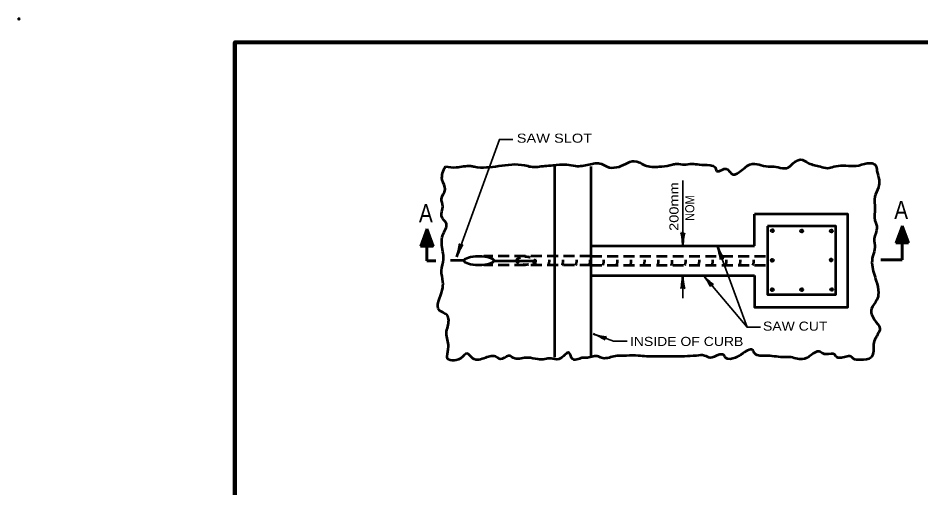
# Model space of a CAD drawing. Extents: x -90 to 623, y -379 to 75.
# Drawn here: x -90.3 to 108.4, y -28.7 to 74.7 of the extents above; entities that cross this region are included whole.
import ezdxf

# ---------------------------------------------------------------- set-up
doc = ezdxf.new("R2010")
doc.units = 0
doc.header["$LTSCALE"] = 0.8
doc.header["$PDMODE"] = 32
doc.header["$PDSIZE"] = 0.4
doc.linetypes.add('MEDIUM_DASHED', pattern=[4.5, 3, -1.5])
doc.linetypes.add('SHORT_DASHED', pattern=[2.7, 1.5, -1.2])
doc.layers.add('1', color=7, linetype='Continuous', lineweight=35)

msp = doc.modelspace()

# ---------------------------------------------------------------- linework, layer by layer
at = {"layer": '1', "lineweight": 53}
for p, q in [((27.7826, 42.0557), (27.7826, 0.0557)), ((35.7826, 42.0557), (35.7826, 0.0557)), ((71.7826, 24.5557), (71.7826, 31.5557)), ((-0.3066, 28.2745), (-1.6747, 24.5158)), ((-0.3066, 28.2745), (1.0615, 24.5158)), ((104.2712, 28.9673), (102.9032, 25.2086)), ((104.2712, 28.9673), (105.6393, 25.2086)), ((35.7826, 24.5557), (71.7826, 24.5557)), ((102.9032, 25.2086), (105.6393, 25.2086)), ((7.8699, 21.3127), (4.8699, 21.3127)), ((14.3764, 21.2934), (23.4164, 21.2934)), ((35.7826, 18.0557), (71.7826, 18.0557))]:
    msp.add_line(p, q, dxfattribs=at)
at = {"layer": '1'}
for p, q in [((56.0009, 24.5898), (56.0009, 38.9634)), ((63.6731, 24.3975), (70.135, 6.6434)), ((56.0009, 13.0557), (56.0009, 18.039))]:
    msp.add_line(p, q, dxfattribs=at)
at = {"layer": '1', "lineweight": 60}
for p, q in [((-0.3066, 21.2745), (-0.3066, 28.2745)), ((104.2712, 21.4673), (104.2712, 28.9673)), ((-1.6747, 24.5158), (1.0615, 24.5158)), ((-0.3066, 21.2745), (1.6934, 21.2745)), ((99.5571, 21.4673), (104.2712, 21.4673))]:
    msp.add_line(p, q, dxfattribs=at)
at = {"layer": '1', "linetype": 'MEDIUM_DASHED', "lineweight": 53}
for p, q in [((35.7826, 22.3057), (12.2447, 22.3057)), ((35.7826, 22.3057), (74.6402, 22.3057)), ((35.7826, 20.3057), (12.2447, 20.3057)), ((35.7826, 20.3057), (74.6402, 20.3057))]:
    msp.add_line(p, q, dxfattribs=at)
at = {"layer": '1', "lineweight": 158}
msp.add_lwpolyline([(617.1938, 69.4188), (-42.5562, 69.3355), (-42.4728, -368.9978)], dxfattribs=at)
at = {"layer": '1'}
for points in [[(6.2503, 22.1841), (15.6422, 47.9881), (18.6423, 47.9881)], [(60.5589, 18.0557), (70.135, 6.6434), (73.135, 6.6434)], [(36.3312, 5.1835), (40.7482, 3.5757), (43.7482, 3.5757)]]:
    msp.add_lwpolyline(points, dxfattribs=at)
at = {"layer": '1', "lineweight": 53}
for points in [[(71.7826, 18.0557), (71.7826, 11.0557), (92.2826, 11.0557), (92.2826, 31.5557), (71.7826, 31.5557)], [(104.893, 26.9856), (103.703, 27.0432), (104.8162, 27.1007), (103.703, 27.1583), (104.7394, 27.1775), (103.7606, 27.2351), (104.7011, 27.2542), (103.8566, 27.3311), (104.7011, 27.3694), (103.7797, 27.427), (104.6435, 27.4846), (103.8757, 27.523), (104.6627, 27.5422), (103.8566, 27.6382), (104.5475, 27.6382), (103.9333, 27.7342), (104.5859, 27.7342), (103.9909, 27.8109), (104.4899, 27.8877), (104.0101, 27.8877), (104.4707, 27.9644), (104.0868, 28.0412), (104.4707, 28.0988), (104.0101, 27.9644), (104.394, 28.1947), (104.0485, 28.1372), (104.4132, 28.3099), (104.0868, 28.2907), (104.3556, 28.3867), (104.202, 28.4443), (104.3364, 28.5211), (104.1828, 28.6363), (103.012, 25.3157), (104.2404, 28.5787), (103.0696, 25.3541), (104.2596, 28.4443), (103.2232, 25.4117), (103.9909, 27.7149), (103.0888, 25.4117), (104.3364, 28.617)], [(104.3364, 28.617), (105.5264, 25.2773), (104.3364, 28.4251), (105.4112, 25.4692), (104.4323, 27.9261), (105.2193, 25.738), (104.3172, 28.0412), (105.0657, 25.9108), (104.7011, 25.8532), (105.1809, 25.6612), (103.2807, 25.6037), (103.2999, 25.7188), (103.607, 25.738), (103.7414, 26.0067), (103.4727, 26.0451), (105.488, 25.3733), (105.0466, 25.9683), (103.7414, 26.0067), (103.5878, 26.1987), (103.0504, 25.3925), (103.8757, 27.2735)], [(102.9928, 25.2773), (105.488, 25.2773), (105.4688, 25.3733), (103.0504, 25.3541), (105.392, 25.4309), (103.0504, 25.4501), (105.3537, 25.5077), (103.1272, 25.5652), (105.3152, 25.6228), (103.2232, 25.5268), (105.4112, 25.5268), (105.2768, 25.738), (103.1656, 25.6804), (105.2577, 25.8148), (103.2615, 25.8148), (105.1425, 25.9491), (103.2999, 25.9299), (105.2193, 26.0259), (103.3767, 26.0642), (105.1617, 26.1411), (103.3767, 26.1794), (105.1425, 26.2178), (103.3959, 26.2754), (105.0657, 26.3138), (103.3959, 26.3522), (105.0466, 26.3714), (103.5302, 26.4097), (105.0273, 26.4673), (103.4727, 26.4673), (104.9506, 26.5825), (103.4918, 26.5442), (104.9314, 26.6593), (103.4918, 26.6209), (104.9506, 26.7361), (103.5302, 26.7168), (104.9506, 26.832), (103.5687, 26.8128), (104.893, 26.9088), (103.607, 26.928), (104.893, 26.9856)]]:
    msp.add_lwpolyline(points, dxfattribs=at)
msp.add_lwpolyline([(74.6402, 28.8667), (74.6402, 13.8667), (89.6402, 13.8667), (89.6402, 28.8667)], close=True, dxfattribs=at)
at = {"layer": '1', "lineweight": 60}
msp.add_lwpolyline([(-1.4583, 24.7103), (0.7682, 24.7487), (0.6914, 24.9406), (-1.3815, 24.9022), (0.5762, 25.1709), (-1.3047, 25.1326), (0.5379, 25.3629), (-1.1895, 25.3629), (0.4995, 25.5932), (-1.1127, 25.6316), (0.4227, 25.8235), (-1.036, 25.8619), (0.154, 26.0538), (-1.0744, 26.1306), (0.3076, 26.0922), (-0.8441, 26.3609), (0.1924, 26.3993), (-0.7672, 26.5528), (-0.0763, 26.5528), (-0.6905, 26.7064), (-0.0379, 26.8216), (-0.6138, 26.8983), (-0.0763, 26.8983), (-0.4986, 26.9752), (-0.4218, 27.5509), (-1.4967, 24.5952), (-0.4218, 27.6661), (-0.0379, 27.0135), (0.9217, 24.6719), (0.2692, 25.67), (0.9985, 24.5567), (0.9217, 24.6335), (0.7682, 24.8254), (-0.0763, 26.7832), (-0.3067, 27.7045), (-0.1147, 27.2438), (-0.2298, 26.2842)], dxfattribs=at)
at = {"layer": '1', "lineweight": 53}
for centre in [(75.7151, 27.8881), (82.1636, 27.8497), (88.6889, 27.8497), (75.6767, 21.4012), (88.6505, 21.4395), (75.6767, 14.9142), (82.1636, 14.9142), (88.7657, 14.9526)]:
    msp.add_circle(centre, 0.25, dxfattribs=at)
at = {"layer": '1', "linetype": 'SHORT_DASHED', "lineweight": 53}
for centre in [(21.4742, 21.2253), (24.4874, 21.2445), (27.5005, 21.2061), (30.5138, 21.2445), (33.4694, 21.2253), (36.4826, 21.2445), (39.4766, 21.2445), (42.4898, 21.2061), (45.4645, 21.2254), (48.5161, 21.2061), (51.5293, 21.187), (54.5041, 21.2254), (57.4981, 21.2445), (60.4729, 21.2254), (63.4669, 21.2062), (66.5185, 21.2062), (69.4743, 21.2254)]:
    msp.add_arc(centre, 2.1707, 334.94384, 29.7373, dxfattribs=at)
at = {"layer": '1', "lineweight": 40}
for centre, major_axis, ratio, start_param, end_param in [((55.7246, 25.681), (0.1562, -1.7857), 0.122415, 0.89635335, 3.14159265), ((56.2125, 25.7103), (0.1757, 1.7565), 0.07063, 6.28230741, 8.55970261), ((6.3639, 23.304), (-0.464, -1.7314), 0.122415, 0.89635335, 3.14159265), ((6.8324, 23.1646), (0.7658, 1.5904), 0.07063, 6.28230741, 8.55970261), ((63.8575, 23.2722), (-0.4357, 1.7106), 0.07063, 3.14071475, 5.41810995), ((64.3059, 23.4666), (-0.7575, 1.6246), 0.122415, 0.89635335, 3.14159265), ((55.7893, 16.9185), (-0.1757, -1.7565), 0.07063, 6.28230741, 8.55970261), ((56.2772, 16.9478), (-0.1562, 1.7857), 0.122415, 0.89635335, 3.14159265), ((61.1171, 17.0613), (0.9945, -1.4584), 0.07063, 6.28230741, 8.55970261), ((61.1171, 17.0613), (0.9945, -1.4584), 0.07063, 6.28230741, 8.55970261), ((61.472, 17.3974), (-1.2674, 1.2675), 0.122415, 0.89635335, 3.14159265), ((61.472, 17.3974), (-1.2674, 1.2675), 0.122415, 0.89635335, 3.14159265), ((37.3118, 4.6014), (1.5904, -0.7658), 0.07063, 6.28230741, 8.55970261), ((37.4511, 5.0699), (-1.7314, 0.464), 0.122415, 0.89635335, 3.14159265)]:
    msp.add_ellipse(centre, major_axis=major_axis, ratio=ratio, start_param=start_param, end_param=end_param, dxfattribs=at)
at = {"layer": '1', "lineweight": 53}
msp.add_ellipse((11.1456, 21.3057), major_axis=(-3.25, 0), ratio=0.300371, dxfattribs=at)
at = {"layer": '1', "linetype": 'SHORT_DASHED', "lineweight": 53}
msp.add_ellipse((21.4166, 21.3057), major_axis=(-2, 0), ratio=0.452986, dxfattribs=at)
at = {"layer": '1', "lineweight": 53}
for points in [[(97.6571, 42.7712), (98.4248, 42.3105), (98.7319, 41.0822), (99.1925, 39.086), (99.039, 37.397), (98.2712, 35.4008), (98.2712, 32.7906), (98.2712, 30.1802), (98.7319, 28.4912), (98.1177, 26.188), (98.2712, 24.1918), (97.8106, 22.3492), (97.6571, 20.3532), (98.5783, 16.8216), (99.039, 14.2112), (98.7319, 12.6757), (97.5035, 10.6797), (98.1177, 8.3764), (99.3461, 6.3803), (98.1177, 3.6164), (97.8106, 0.699), (97.5035, 0.0848), (95.0468, -0.5293), (93.5113, -0.2223), (93.2042, 0.0848), (90.9009, -0.0687), (89.6726, 0.2384), (89.519, 0.5455), (87.5229, 0.699), (86.9087, 0.8526), (85.9874, 1.3133), (84.2983, 0.5455), (82.3023, -0.3758), (79.3848, 0.0848), (78.0029, 0.0848), (74.3178, 0.3919), (72.9358, 0.3919), (71.861, 0.8526), (71.4003, 1.6203), (68.9436, 0.699), (68.4829, 0.3919), (67.5617, -0.0687), (65.412, -0.0687), (64.9513, 0.5455), (63.8765, 0.5455), (62.0339, -0.0687), (60.8055, 0.3919), (58.9629, 0.3919), (56.3527, 0.2384), (54.6636, 0.2384), (51.5927, 0.2384), (49.5965, 0.2384), (48.0611, 0.2384), (46.2185, 0.3919), (43.6082, 0.3919), (40.8443, 0.2384), (38.0804, -0.0687), (37.4663, 0.2384), (35.0095, -0.0687), (34.0882, -0.0687), (33.0133, -0.3758), (31.785, -0.3758), (31.0173, 1.0061), (28.714, -0.3758), (27.025, -0.2223), (25.6431, -0.3758), (24.1076, -0.3758), (21.9579, -0.0687), (20.4224, -0.2223), (19.0405, -0.2223), (17.6586, 0.3919), (15.816, -0.3758), (15.0482, 0.0848), (12.5915, -0.0687), (9.8276, -0.2223), (8.5992, 0.8526), (7.0637, -0.2223), (4.1463, 0.0848), (4.1463, 0.2384), (4.4534, 2.3881), (3.9928, 5.3054), (4.2999, 6.8409), (4.1463, 9.2977), (2.4573, 10.3725), (3.0715, 14.8254), (3.2251, 16.668), (2.9179, 19.1247), (3.3786, 21.5816), (3.2251, 23.2706), (3.2251, 26.9557), (3.9928, 29.4125), (2.9179, 31.1015), (3.2251, 33.2512), (2.9179, 34.9402), (3.6857, 36.9363), (3.0715, 39.086), (3.7826, 42.0557)], [(3.7826, 42.0557), (6.1424, 41.8498), (9.367, 42.157), (10.1347, 42.0034), (15.5089, 42.157), (21.1902, 42.3105), (22.5721, 42.0034), (25.6431, 42.157), (27.4856, 42.3105), (30.403, 42.4641), (32.3992, 42.157), (35.3166, 42.4641), (38.0804, 42.6176), (39.3088, 42.0034), (41.4585, 41.8498), (43.4546, 42.6176), (45.2972, 43.2318), (47.6004, 42.3105), (50.8249, 42.0034), (53.1282, 42.3105), (53.7423, 42.4641), (54.6636, 42.6176), (56.3527, 42.4641), (58.0417, 42.6176), (59.5772, 42.4641), (62.0339, 42.3105), (63.1088, 41.8498), (63.4158, 41.0822), (65.412, 41.5427), (65.5655, 41.5427), (66.6403, 40.4679), (70.7862, 42.4641), (72.7822, 42.4641), (74.7784, 42.0034), (76.0067, 42.0034), (79.5384, 42.0034), (79.6919, 42.157), (80.9203, 43.2318), (81.8416, 43.5389), (83.6842, 42.7712), (86.2945, 42.0034), (87.83, 41.6963), (89.2119, 42.0034), (93.5113, 42.157), (94.1254, 42.157), (96.5822, 42.7712), (97.6571, 42.7712)]]:
    msp.add_spline(points, degree=3, dxfattribs=at)
at = {"layer": '1'}
msp.add_point((-90.0562, 74.5022), dxfattribs=at)

# ---------------------------------------------------------------- texts
for s, height, width, p in [('SAW SLOT', 2, 1.2, (19.47, 47.2657)), ('A', 4, 0.85, (102.5354, 30.4629)), ('A', 4, 0.85, (-2.0417, 29.7547)), ('SAW CUT', 2, 1.15, (73.6469, 5.8954)), ('INSIDE OF CURB', 2, 1.15, (44.3749, 2.5315))]:
    msp.add_text(s, height=height, dxfattribs=dict(at, width=width)).set_placement(p)
for s, width, p in [('200mm', 1.2, (55.0553, 27.8575)), ('NOM', 0.9, (58.5386, 30.0667))]:
    msp.add_text(s, height=2, rotation=90, dxfattribs=dict(at, width=width)).set_placement(p)

doc.saveas('drawing.dxf')
